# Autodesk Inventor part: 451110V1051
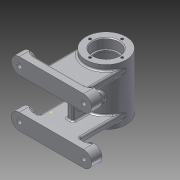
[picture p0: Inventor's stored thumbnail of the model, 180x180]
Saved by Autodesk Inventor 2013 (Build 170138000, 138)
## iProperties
Created: 2015-11
Part Number: 451110V1051
Material: 알루미늄 6061
Document SubType Name: Modeling
Designer: Administrator
Density: 2.71 g/cm^3
Mass: 359.156 g
Surface Area: 459.471 cm^2
Volume: 132.53 cm^3
Author: Administrator
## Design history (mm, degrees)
sketch "스케치1"
  geometry: C1 r 25 at (0, 0); 1 further point
  constraints: 1 centre point, 1 coincident
  dimensions: "d0" = 50 diameter of C1
extrude "돌출1" new body sketch "스케치1" stored distance "d1" = 70; taper "d2" = 0 deg
sketch "스케치2"
  geometry: C1 r 25 at (0, 0) reference; C2 r 16 at (0, 0)
  constraints: 1 centre point, 1 coincident
  dimensions: "d3" = 32 diameter of C2
extrude "돌출2" cut sketch "스케치2" distance "d4" = 12; taper "d5" = 0 deg
sketch "스케치3"
  geometry: C1 r 16 at (0, 0) reference; C2 r 14 at (0, 0)
  constraints: 1 centre point, 1 coincident
  dimensions: "d6" = 28 diameter of C2
extrude "돌출3" cut sketch "스케치3" distance "d7" = 2; taper "d8" = 0 deg
sketch "스케치4"
  geometry: C1 r 14 at (0, 0) reference; C2 r 21 at (0, 0)
  constraints: 1 centre point, 1 coincident
  dimensions: "d9" = 42 diameter of C2
extrude "돌출4" cut sketch "스케치4" distance "d10" = 42; taper "d11" = 0 deg
node "작업 평면1"
sketch "스케치5"
  geometry: C1 r 5 at (0, 0); 1 further point
  constraints: 1 centre point, 1 coincident
  dimensions: "d13" = 10 diameter of C1
extrude "돌출5" join sketch "스케치5" stored distance "d14" = 42; taper "d15" = 0 deg
sketch "스케치6"
  geometry: C1 r 5 at (0, 0) reference
hole "구멍1" sketch "스케치6" at (0, 0) diameter "d16" = 5.188; stored, may be unused: countersink angle "d20" = 90 deg, drill point angle "d22" = 118 deg; dims "d17" = 20, "d18" = 4, "d19" = 2, "d21" = 20
sketch "스케치7"
  geometry: L1 (0, 0)-(14, -24.249); L2 (0, 0)-(0, -37.188)
  constraints: 4 end point, 1 vertical
  dimensions: "d23" = 28 distance of L1.start L1.end; "d24" = 30 deg angle of L1 L2
node "작업 평면2"
sketch "스케치8"
  geometry: C1 r 6 at (0, 0); 1 further point
  constraints: 1 centre point, 1 coincident
  dimensions: "d25" = 12 diameter of C1
extrude "돌출6" join sketch "스케치8" stored distance "d26" = 42; taper "d27" = 0 deg
sketch "스케치9"
  geometry: C1 r 6 at (0, 0) reference
hole "구멍2" sketch "스케치9" at (0, 0) diameter "d28" = 5.188; stored, may be unused: countersink angle "d32" = 90 deg, drill point angle "d34" = 118 deg; dims "d29" = 20, "d30" = 4, "d31" = 2, "d33" = 20
node "작업 평면3"
sketch "스케치10"
  geometry: 1 further point
sketch "스케치11"
  geometry: L1 (40, 40)-(-40, 40); L2 (-40, 40)-(-40, -40); L3 (-40, -40)-(40, -40); L4 (40, -40)-(40, 40); L5 (40, 40)-(-40, -40); L6 (-40, 40)-(40, -40); L7 (0, 0)-(0, -20); L8 (0, -20)-(40, -20); L9 (0, -20)-(-40, -20); L10 (0, 0)-(0, 20); L11 (0, 20)-(40, 20); L12 (0, 20)-(-40, 20)
  constraints: 24 end point, 6 perpendicular, 4 point on line, 3 parallel, 2 midpoint, 1 horizontal
  dimensions: "d36" = 80 distance of L3.end L2.end; "d37" = 80 distance of L2.end L1.end; "d38" = 20 distance of L7.start L7.end; "d39" = 20 distance of L7.start L10.end
extrude "돌출7" join sketch "스케치11" distance "d40" = 10; taper "d41" = 0 deg
sketch "스케치12"
  geometry: L1 (40, -40)-(40, -20) reference; L2 (-40, -20)-(-40, -40) reference; L3 (40, 40)-(-40, 40) reference; L4 (40, 20)-(40, 40) reference; L5 (-40, 20)-(40, 20) reference; L6 (-40, 40)-(-40, 20) reference; C1 r 10 at (-40, -30); C2 r 10 at (40, -30); C3 r 10 at (-40, 30); C4 r 10 at (40, 30); 1 further point
  constraints: 4 centre point, 4 midpoint
  dimensions: "d42" = 20 diameter of C1; "d43" = 20 diameter of C2; "d44" = 20 diameter of C3; "d45" = 20 diameter of C4
extrude "돌출8" join sketch "스케치12" distance "d46" = 3; taper "d48" = 0 deg; dims "d47" = 10, "d49" = 0
sketch "스케치13"
  geometry: L1 (40, -20)-(-40, -20) reference; L2 (0, 0)-(0, -20); L3 (0, -20)-(0, -24); L4 (-25, -28)-(25, -28); L5 (25, -28)-(25, -20); L6 (25, -20)-(-25, -20); L7 (-25, -20)-(-25, -28); L8 (-25, -28)-(25, -20); L9 (25, -28)-(-25, -20)
  constraints: 16 end point, 3 midpoint, 2 parallel, 1 collinear, 1 horizontal, 1 perpendicular
  dimensions: "d50" = 20 distance of L2.start L2.end; "d52" = 4 distance of L2.end L3.end; "d53" = 50 distance of L6.end L5.end; "d54" = 8 distance of L5.end L4.end
extrude "돌출9" join sketch "스케치13" stored distance "d55" = 3; taper "d56" = 0 deg
sketch "스케치14"
  geometry: C1 r 10 at (0, 0) reference; C2 r 10 at (0, 60) reference; C3 r 10 at (80, 60) reference; C4 r 10 at (80, 0) reference; 1 further point
hole "구멍3" sketch "스케치14" at (0, 60), (0, 0), (80, 0), (80, 60) diameter "d57" = 6; stored, may be unused: countersink angle "d61" = 90 deg, drill point angle "d63" = 118 deg; dims "d58" = 6, "d59" = 12, "d60" = 4, "d62" = 20
chamfer "모따기1" distance "d64" = 1; stored, may be unused: second distance "d65" = 2, angle "d66" = 45 deg
sketch "스케치15" dims "d67" = 40
  geometry: L1 (0, 0)-(0, 20); C1 r 25 at (0, 0) reference
  constraints: 2 end point, 1 coincident, 1 vertical, 1 vertical alignment, 2 other
hole "구멍4" sketch "스케치15" at (0, 20) diameter "d68" = 3.242; stored, may be unused: countersink angle "d72" = 90 deg, drill point angle "d74" = 118 deg; dims "d69" = 8, "d70" = 12, "d71" = 4, "d73" = 10
sketch "스케치16" dims "d31" = 2, "d78" = 40
  geometry: L1 (0, 0)-(0, 20); C1 r 25 at (0, 0) reference
  constraints: 2 end point, 1 coincident, 1 vertical, 1 vertical alignment, 2 other
hole "구멍5" sketch "스케치16" at (0, 20) diameter "d79" = 3.242; stored, may be unused: countersink angle "d83" = 90 deg, drill point angle "d85" = 118 deg; dims "d80" = 8, "d81" = 12, "d82" = 4, "d84" = 10
sketch "스케치17"
  geometry: L1 (0, 0)-(-25, 0); L2 (-25, 0)-(-35, 0); L3 (-45, -20)-(-25, -20); L4 (-25, -20)-(-25, 20); L5 (-25, 20)-(-45, 20); L6 (-45, 20)-(-45, -20); L7 (-45, -20)-(-25, 20); L8 (-25, -20)-(-45, 20); L9 (-25, 20)-(-23, 20); L10 (-23, 20)-(-23, -20); L11 (-23, -20)-(-25, -20)
  constraints: 22 end point, 3 perpendicular, 2 horizontal, 2 midpoint, 2 parallel, 1 collinear
  dimensions: "d89" = 25 distance of L1.start L1.end; "d90" = 10 distance of L1.end L2.end; "d91" = 20 distance of L5.end L4.end; "d92" = 40 distance of L4.end L3.end
extrude "돌출10" join sketch "스케치17" stored distance "d93" = 8; taper "d94" = 0 deg
sketch "스케치18"
  geometry: L1 (20, -25)-(-20, -25) reference; L2 (-20, -45)-(20, -45) reference; L3 (0, -25)-(0, -35); L4 (8, -38.5)-(-8, -38.5); L5 (-11.5, -35)-(-11.5, -35); L6 (-8, -31.5)-(8, -31.5); L7 (11.5, -35)-(11.5, -35); L8 (11.5, -38.5)-(-11.5, -31.5); L9 (-11.5, -38.5)-(11.5, -31.5); A1 r 3.5 centre (-8, -35) between (-8, -31.5) and (-11.5, -35); A2 r 3.5 centre (-8, -35) between (-11.5, -35) and (-8, -38.5); A3 r 3.5 centre (8, -35) between (11.5, -35) and (8, -31.5); A4 r 3.5 centre (8, -35) between (8, -38.5) and (11.5, -35); 1 further point
  constraints: 14 end point, 8 point on circle, 8 point on line, 8 tangent, 4 centre point, 3 equal radius, 3 midpoint, 2 parallel, 2 perpendicular, 1 horizontal
  dimensions: "d95" = 10 distance of L3.start L3.end; "d96" = 23 distance of L8.end L9.end; "d97" = 7 distance of L9.start L8.end; "d98" = 3.5 radius of A1
extrude "돌출11" cut sketch "스케치18" distance "d99" = 8; taper "d100" = 0 deg
node "작업 평면4"
sketch "스케치19"
  geometry: L1 (-25, -35)-(25, -35) reference; L2 (-25, -35)-(-25, 35) reference; L3 (0, -28)-(0, -20) reference; 2 further points
  constraints: 1 other
  dimensions: "d102" = 35 distance from line of L1 point (0, 0); "d104" = 25 distance from line of L2 point (0, 0)
feature "엠보싱1" sketch "스케치19" dims "d105" = 0.5, "d106" = 0
extrude "돌출12" join sketch "스케치17" stored distance "d107" = 8; taper "d108" = 0 deg
fillet "모깎기1" dims "d109" = 2
fillet "모깎기2" dims "d110" = 2
fillet "모깎기3" dims "d111" = 2, "d112" = 2
fillet "모깎기4" dims "d113" = 2, "d114" = 2
fillet "모깎기5" dims "d115" = 2
fillet "모깎기6" dims "d116" = 2
fillet "모깎기7" dims "d117" = 2
fillet "모깎기8" dims "d118" = 2, "d119" = 3
fillet "모깎기9" dims "d120" = 0.3
chamfer "모따기2" distance "d121" = 1; stored, may be unused: second distance "d122" = 2, angle "d123" = 45 deg
node "솔리드1"
mirror "대칭1"
mirror "대칭2"
pattern_circular "원형 패턴1" dims angle "d76" = 360 deg
pattern_circular "원형 패턴2" dims angle "d87" = 360 deg
node "투영된 루프1"
node "투영된 루프2"
node "투영된 루프3"
other parameters: "d12" = 28, "d35" = -68, "d101" = -25
